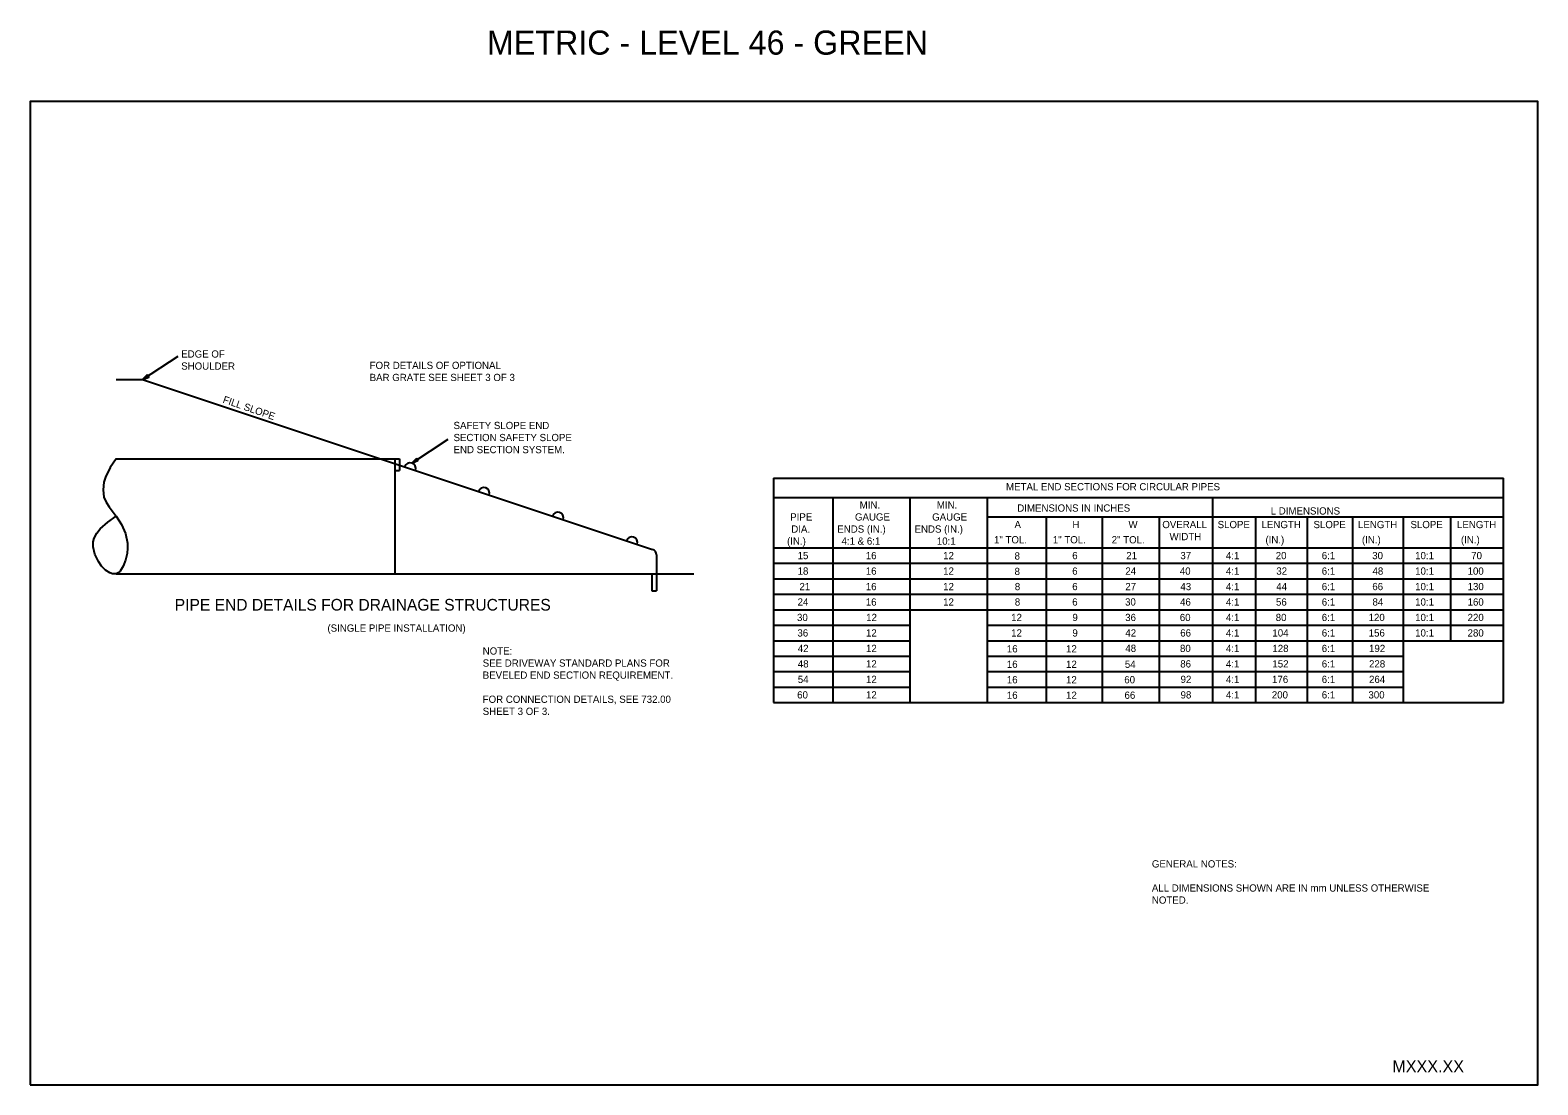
# Model space of a CAD drawing. Extents: x -439.1 to -407.9, y -458.1 to -436.2.
import ezdxf

# ---------------------------------------------------------------- set-up
doc = ezdxf.new("R2010")
doc.units = 0
for name, color, linetype in [('Bridge-Named Boundary', 7, 'Continuous'), ('Default', 7, 'Continuous'), ('Level 46', 7, 'Continuous')]:
    doc.layers.add(name, color=color, linetype=linetype)

msp = doc.modelspace()

# ---------------------------------------------------------------- linework, layer by layer
at = {"layer": 'Bridge-Named Boundary'}
msp.add_lwpolyline([(-439.109, -458.051), (-407.859, -458.051), (-407.859, -437.676), (-439.109, -437.676)], close=True, dxfattribs=at)
at = {"layer": 'Default'}
for p, q in [((-436.777, -443.434), (-436.041, -442.949)), ((-437.326, -443.434), (-436.777, -443.434)), ((-436.777, -443.434), (-426.207, -446.958)), ((-431.2, -445.168), (-430.448, -444.673)), ((-437.326, -445.081), (-431.455, -445.081)), ((-431.551, -445.081), (-431.551, -447.463)), ((-431.455, -445.081), (-431.455, -445.319)), ((-431.551, -445.319), (-431.455, -445.319)), ((-423.7, -445.479), (-408.57, -445.479)), ((-423.7, -445.479), (-423.7, -450.13)), ((-408.57, -450.13), (-408.57, -445.479)), ((-423.7, -445.879), (-408.573, -445.879)), ((-422.466, -450.13), (-422.466, -445.879)), ((-420.866, -450.13), (-420.866, -445.879)), ((-419.266, -450.13), (-419.266, -445.879)), ((-414.597, -450.13), (-414.597, -445.879)), ((-419.266, -446.281), (-408.573, -446.281)), ((-418.046, -450.13), (-418.046, -446.281)), ((-416.879, -450.13), (-416.879, -446.281)), ((-415.701, -450.13), (-415.701, -446.281)), ((-413.701, -450.13), (-413.701, -446.281)), ((-412.634, -450.13), (-412.634, -446.281)), ((-411.691, -450.13), (-411.691, -446.281)), ((-410.644, -450.13), (-410.644, -446.281)), ((-409.66, -448.848), (-409.66, -446.281)), ((-426.126, -447.07), (-426.126, -447.817)), ((-423.7, -446.924), (-408.57, -446.924)), ((-437.326, -447.461), (-425.354, -447.461)), ((-426.22, -447.461), (-426.22, -447.817)), ((-423.7, -447.244), (-408.57, -447.244)), ((-423.7, -447.565), (-408.57, -447.565)), ((-426.22, -447.817), (-426.126, -447.817)), ((-423.7, -447.886), (-408.57, -447.886)), ((-423.7, -448.206), (-408.57, -448.206)), ((-423.7, -448.527), (-420.866, -448.527)), ((-419.266, -448.527), (-408.57, -448.527)), ((-423.7, -448.848), (-420.866, -448.848)), ((-419.266, -448.848), (-408.57, -448.848)), ((-423.7, -449.169), (-420.866, -449.169)), ((-419.266, -449.169), (-410.644, -449.169)), ((-423.7, -449.488), (-420.866, -449.488)), ((-419.266, -449.488), (-410.644, -449.488)), ((-423.7, -449.809), (-420.866, -449.809)), ((-419.266, -449.809), (-410.644, -449.809)), ((-423.7, -450.13), (-408.57, -450.13))]:
    msp.add_line(p, q, dxfattribs=at)
for points in [[(-436.681, -443.337), (-436.777, -443.434), (-436.651, -443.384)], [(-431.103, -445.071), (-431.2, -445.168), (-431.073, -445.117)]]:
    msp.add_lwpolyline(points, close=True, dxfattribs=at)
msp.add_lwpolyline([(-437.326, -445.081), (-437.451, -445.259), (-437.547, -445.461), (-437.579, -445.565), (-437.599, -445.722), (-437.58, -445.871), (-437.536, -445.976), (-437.474, -446.076), (-437.326, -446.271), (-437.216, -446.442), (-437.135, -446.625), (-437.094, -446.824), (-437.091, -446.93), (-437.101, -447.042), (-437.13, -447.178), (-437.179, -447.305), (-437.245, -447.405), (-437.284, -447.44), (-437.326, -447.46), (-437.399, -447.463), (-437.457, -447.444), (-437.544, -447.386), (-437.628, -447.302), (-437.695, -447.21), (-437.77, -447.057), (-437.806, -446.901), (-437.8, -446.797), (-437.78, -446.724), (-437.728, -446.623), (-437.657, -446.531), (-437.497, -446.389), (-437.326, -446.271)], dxfattribs=at)
for centre, start, end in [((-431.237, -445.281), 341.5668, 161.565), ((-429.705, -445.791), 341.567, 161.5652), ((-428.172, -446.302), 341.5684, 161.5659), ((-426.639, -446.813), 341.5678, 161.5623), ((-426.245, -447.07), 0, 71.5649)]:
    msp.add_arc(centre, 0.119, start, end, dxfattribs=at)

# ---------------------------------------------------------------- texts
for s, height, p in [('SHOULDER', 0.15, (-435.978, -443.232)), ('EDGE OF ', 0.15, (-435.978, -442.982)), ('FOR DETAILS OF OPTIONAL ', 0.15, (-432.072, -443.218)), ('BAR GRATE SEE SHEET 3 OF 3', 0.15, (-432.072, -443.468)), ('SAFETY SLOPE END ', 0.15, (-430.333, -444.463)), ('SECTION SAFETY SLOPE ', 0.15, (-430.333, -444.713)), ('END SECTION SYSTEM.', 0.15, (-430.333, -444.963)), ('METAL END SECTIONS FOR CIRCULAR PIPES', 0.15, (-418.882, -445.732)), ('PIPE', 0.15, (-423.355, -446.359)), ('GAUGE', 0.15, (-422.013, -446.359)), ('MIN.', 0.15, (-421.916, -446.109)), ('GAUGE', 0.15, (-420.413, -446.359)), ('MIN.', 0.15, (-420.316, -446.109)), ('DIMENSIONS IN INCHES', 0.15, (-418.649, -446.174)), ('L DIMENSIONS', 0.15, (-413.396, -446.234)), ('DIA.', 0.15, (-423.333, -446.609)), ('ENDS (IN.)', 0.15, (-422.379, -446.609)), ('ENDS (IN.)', 0.15, (-420.778, -446.609)), ('A', 0.15, (-418.706, -446.516)), ('H', 0.15, (-417.506, -446.516)), ('W', 0.15, (-416.344, -446.516)), ('OVERALL', 0.15, (-415.643, -446.516)), ('SLOPE', 0.15, (-414.496, -446.516)), ('LENGTH', 0.15, (-413.586, -446.516)), ('SLOPE', 0.15, (-412.509, -446.516)), ('LENGTH', 0.15, (-411.586, -446.516)), ('SLOPE', 0.15, (-410.499, -446.516)), ('LENGTH', 0.15, (-409.534, -446.516)), ('(IN.)', 0.15, (-423.421, -446.859)), ('4:1 & 6:1', 0.15, (-422.291, -446.859)), ('10:1', 0.15, (-420.316, -446.859)), ('1" TOL.', 0.15, (-419.131, -446.831)), ('1" TOL.', 0.15, (-417.912, -446.831)), ('2" TOL.', 0.15, (-416.692, -446.831)), ('WIDTH', 0.15, (-415.493, -446.766)), ('(IN.)', 0.15, (-413.505, -446.831)), ('(IN.)', 0.15, (-411.505, -446.831)), ('(IN.)', 0.15, (-409.453, -446.831)), ('15', 0.15, (-423.202, -447.159)), ('16', 0.15, (-421.789, -447.159)), ('12', 0.15, (-420.185, -447.159)), ('8', 0.15, (-418.705, -447.167)), ('6', 0.15, (-417.51, -447.159)), ('21', 0.15, (-416.39, -447.159)), ('37', 0.15, (-415.268, -447.159)), ('4:1', 0.15, (-414.324, -447.159)), ('20', 0.15, (-413.292, -447.159)), ('6:1', 0.15, (-412.338, -447.159)), ('30', 0.15, (-411.292, -447.159)), ('10:1', 0.15, (-410.402, -447.159)), ('70', 0.15, (-409.24, -447.159)), ('18', 0.15, (-423.202, -447.48)), ('16', 0.15, (-421.789, -447.48)), ('12', 0.15, (-420.185, -447.48)), ('8', 0.15, (-418.705, -447.488)), ('6', 0.15, (-417.51, -447.48)), ('24', 0.15, (-416.409, -447.48)), ('40', 0.15, (-415.28, -447.48)), ('4:1', 0.15, (-414.324, -447.48)), ('32', 0.15, (-413.28, -447.48)), ('6:1', 0.15, (-412.338, -447.48)), ('48', 0.15, (-411.286, -447.48)), ('10:1', 0.15, (-410.402, -447.48)), ('100', 0.15, (-409.315, -447.48)), ('21', 0.15, (-423.164, -447.801)), ('16', 0.15, (-421.789, -447.801)), ('12', 0.15, (-420.185, -447.801)), ('8', 0.15, (-418.7, -447.801)), ('6', 0.15, (-417.51, -447.801)), ('27', 0.15, (-416.409, -447.801)), ('43', 0.15, (-415.268, -447.801)), ('4:1', 0.15, (-414.324, -447.801)), ('44', 0.15, (-413.28, -447.801)), ('6:1', 0.15, (-412.338, -447.801)), ('66', 0.15, (-411.29, -447.801)), ('10:1', 0.15, (-410.402, -447.801)), ('130', 0.15, (-409.315, -447.801)), ('PIPE END DETAILS FOR DRAINAGE STRUCTURES', 0.24169, (-436.112, -448.224)), ('24', 0.15, (-423.202, -448.12)), ('16', 0.15, (-421.789, -448.121)), ('12', 0.15, (-420.185, -448.121)), ('8', 0.15, (-418.7, -448.12)), ('6', 0.15, (-417.51, -448.12)), ('30', 0.15, (-416.415, -448.12)), ('46', 0.15, (-415.275, -448.121)), ('4:1', 0.15, (-414.324, -448.121)), ('56', 0.15, (-413.287, -448.121)), ('6:1', 0.15, (-412.338, -448.121)), ('84', 0.15, (-411.286, -448.12)), ('10:1', 0.15, (-410.402, -448.121)), ('160', 0.15, (-409.315, -448.121)), ('30', 0.15, (-423.214, -448.441)), ('12', 0.15, (-421.781, -448.441)), ('12', 0.15, (-418.775, -448.441)), ('9', 0.15, (-417.506, -448.441)), ('36', 0.15, (-416.412, -448.441)), ('60', 0.15, (-415.28, -448.441)), ('4:1', 0.15, (-414.324, -448.441)), ('80', 0.15, (-413.292, -448.441)), ('6:1', 0.15, (-412.338, -448.441)), ('120', 0.15, (-411.367, -448.441)), ('10:1', 0.15, (-410.402, -448.441)), ('220', 0.15, (-409.315, -448.441)), ('(SINGLE PIPE INSTALLATION)', 0.15, (-432.947, -448.661)), ('36', 0.15, (-423.206, -448.762)), ('12', 0.15, (-421.785, -448.762)), ('12', 0.15, (-418.775, -448.762)), ('9', 0.15, (-417.506, -448.762)), ('42', 0.15, (-416.409, -448.762)), ('66', 0.15, (-415.271, -448.762)), ('4:1', 0.15, (-414.324, -448.762)), ('104', 0.15, (-413.361, -448.762)), ('6:1', 0.15, (-412.338, -448.762)), ('156', 0.15, (-411.365, -448.762)), ('10:1', 0.15, (-410.402, -448.762)), ('280', 0.15, (-409.315, -448.762)), ('NOTE:', 0.15, (-429.729, -449.136)), ('42', 0.15, (-423.198, -449.083)), ('12', 0.15, (-421.785, -449.083)), ('16', 0.15, (-418.865, -449.091)), ('12', 0.15, (-417.638, -449.091)), ('48', 0.15, (-416.409, -449.08)), ('80', 0.15, (-415.276, -449.083)), ('4:1', 0.15, (-414.324, -449.083)), ('128', 0.15, (-413.361, -449.083)), ('6:1', 0.15, (-412.338, -449.083)), ('192', 0.15, (-411.358, -449.083)), ('SEE DRIVEWAY STANDARD PLANS FOR ', 0.15, (-429.729, -449.386)), ('48', 0.15, (-423.198, -449.403)), ('12', 0.15, (-421.785, -449.403)), ('16', 0.15, (-418.865, -449.411)), ('12', 0.15, (-417.638, -449.411)), ('54', 0.15, (-416.419, -449.411)), ('86', 0.15, (-415.271, -449.403)), ('4:1', 0.15, (-414.324, -449.403)), ('152', 0.15, (-413.361, -449.403)), ('6:1', 0.15, (-412.338, -449.403)), ('228', 0.15, (-411.358, -449.403)), ('BEVELED END SECTION REQUIREMENT.', 0.15, (-429.729, -449.636)), ('54', 0.15, (-423.198, -449.724)), ('12', 0.15, (-421.785, -449.724)), ('16', 0.15, (-418.865, -449.731)), ('12', 0.15, (-417.638, -449.731)), ('60', 0.15, (-416.431, -449.731)), ('92', 0.15, (-415.264, -449.724)), ('4:1', 0.15, (-414.324, -449.724)), ('176', 0.15, (-413.368, -449.724)), ('6:1', 0.15, (-412.338, -449.724)), ('264', 0.15, (-411.358, -449.724)), ('FOR CONNECTION DETAILS, SEE 732.00', 0.15, (-429.729, -450.136)), ('60', 0.15, (-423.211, -450.045)), ('12', 0.15, (-421.785, -450.045)), ('16', 0.15, (-418.865, -450.052)), ('12', 0.15, (-417.638, -450.052)), ('66', 0.15, (-416.426, -450.052)), ('98', 0.15, (-415.264, -450.045)), ('4:1', 0.15, (-414.324, -450.045)), ('200', 0.15, (-413.373, -450.045)), ('6:1', 0.15, (-412.338, -450.045)), ('300', 0.15, (-411.37, -450.045)), ('SHEET 3 OF 3.', 0.15, (-429.729, -450.386))]:
    msp.add_text(s, height=height, dxfattribs=at).set_placement(p)
msp.add_text('FILL SLOPE', height=0.15, rotation=340.9912, dxfattribs=at).set_placement((-435.128, -443.913))
at = {"layer": 'Level 46'}
for s, height, p in [('METRIC - LEVEL 46 - GREEN', 0.5, (-429.642, -436.705)), ('GENERAL NOTES:', 0.15, (-415.859, -453.547)), ('ALL DIMENSIONS SHOWN ARE IN mm UNLESS OTHERWISE ', 0.15, (-415.859, -454.047)), ('NOTED.', 0.15, (-415.859, -454.297)), ('MXXX.XX', 0.25, (-410.875, -457.792))]:
    msp.add_text(s, height=height, dxfattribs=at).set_placement(p)

doc.saveas('drawing.dxf')
